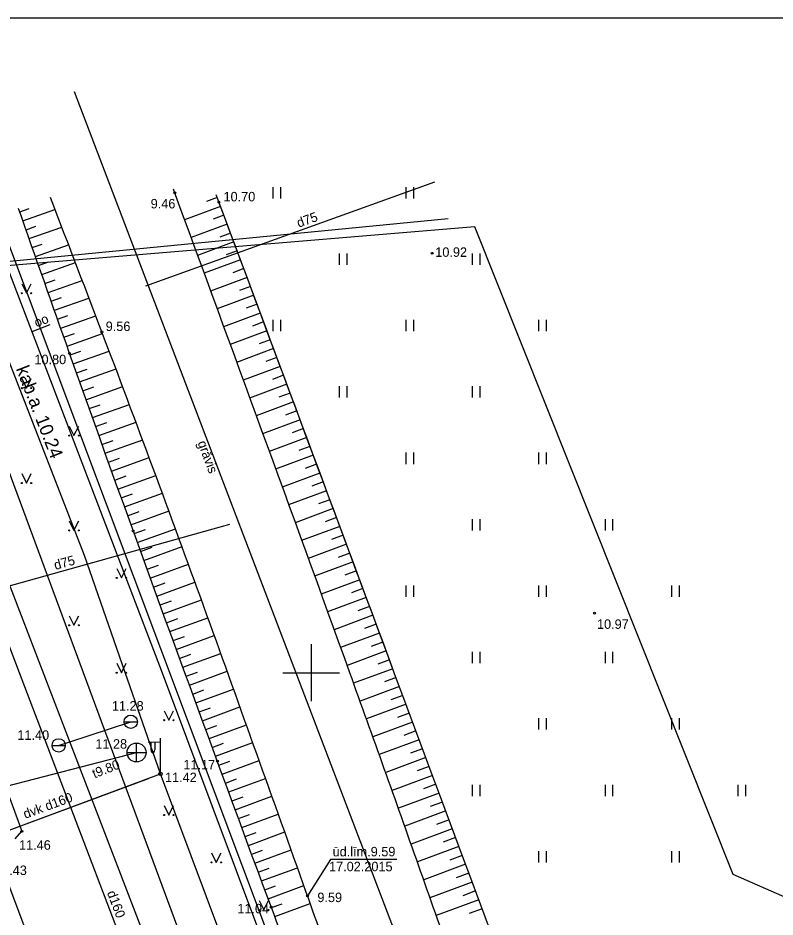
# Model space of a CAD drawing. Extents: x 503353 to 504004, y 304662 to 305049.
# Drawn here: x 503384.55 to 503424.44, y 304987.12 to 305034.51 of the extents above; entities that cross this region are included whole.
import ezdxf

# ---------------------------------------------------------------- set-up
doc = ezdxf.new("R2010")
doc.units = 0
for name, color, linetype in [('25', 7, 'Continuous'), ('APGR_SARK_####_####_#', 7, 'Continuous'), ('APGS_ACRL_####_####_#', 7, 'Continuous'), ('APGS_ACRL_####_TKST_#', 7, 'Continuous'), ('APGS_ELEM_####_####_#', 7, 'Continuous'), ('APGS_VADP_ZSPR_####_#', 7, 'Continuous'), ('APGS_VADP_ZSPR_TKST_#', 7, 'Continuous'), ('CELI_CMAL_####_####_#', 7, 'Continuous'), ('DREN_VADP_KLKT_####_#', 7, 'Continuous'), ('DREN_VADP_KLKT_TKST_#', 7, 'Continuous'), ('ELEK_VADP_ZSPR_####_#', 7, 'Continuous'), ('GAZE_VADP_VSP2_####_#', 7, 'Continuous'), ('GAZE_VADP_VSP2_TKST_#', 7, 'Continuous'), ('GEOD_ELEM_####_####_#', 7, 'Continuous'), ('HIDG_GRAV_####_TKST_#', 7, 'Continuous'), ('HIDG_PLIN_####_####_#', 7, 'Continuous'), ('HIDG_UATZ_####_TKST_#', 7, 'Continuous'), ('RAMI_PLAN_####_TKST_#', 7, 'Continuous'), ('RAMI_UZMR_####_####_#', 7, 'Continuous'), ('RELJ_AATZ_####_TKST_#', 7, 'Continuous'), ('RELJ_ELEM_####_####_#', 7, 'Continuous'), ('RELJ_NOGA_####_####_#', 7, 'Continuous'), ('SAKK_IZVK_####_TKST_#', 7, 'Continuous'), ('SAKK_KKAN_####_####_#', 7, 'Continuous'), ('SKAN_ELEM_####_####_#', 7, 'Continuous'), ('SKAN_ELEM_PAST_TKST_#', 7, 'Continuous'), ('SKAN_VADP_PAST_####_#', 7, 'Continuous'), ('SKAN_VADP_PAST_TKST_#', 7, 'Continuous'), ('TERT_ELEM_####_####_#', 7, 'Continuous'), ('UDTK_ELEM_####_####_#', 7, 'Continuous'), ('UDTK_ELEM_####_TKST_#', 7, 'Continuous'), ('UDTK_VADP_UDEN_####_#', 7, 'Continuous')]:
    doc.layers.add(name, color=color, linetype=linetype)

msp = doc.modelspace()

# ---------------------------------------------------------------- linework, layer by layer
at = {"layer": '25'}
for p, q in [((503395.906, 305008.647), (503387.533, 305030.611)), ((503405.924, 304982.367), (503395.906, 305008.647))]:
    msp.add_line(p, q, dxfattribs=at)
at = {"layer": 'APGR_SARK_####_####_#'}
msp.add_line((503382.16, 305027.621), (503400.006, 304980.111), dxfattribs=at)
at = {"layer": 'APGS_ACRL_####_####_#'}
msp.add_line((503382.983, 304991.303), (503391.423, 304994.43), dxfattribs=at)
at = {"layer": 'APGS_ELEM_####_####_#'}
for p, q in [((503392.05, 304996.333), (503391.415, 304996.328)), ((503391.55, 304996.329), (503391.55, 304995.937)), ((503391.76, 304996.331), (503391.76, 304995.937)), ((503392.059, 304994.666), (503392.057, 304996.549))]:
    msp.add_line(p, q, dxfattribs=at)
msp.add_circle((503392.059, 304994.666), 0.0907, dxfattribs=at)
msp.add_ellipse((503391.655, 304995.937), major_axis=(0, 0.151), ratio=0.695971, start_param=1.570796, end_param=4.712389, dxfattribs=at)
at = {"layer": 'APGS_VADP_ZSPR_####_#'}
for p, q in [((503388.049, 305006.178), (503380.972, 305024.384)), ((503390.197, 305000.011), (503388.049, 305006.178)), ((503392.059, 304994.666), (503390.197, 305000.011)), ((503382.828, 304991.246), (503392.059, 304994.666)), ((503395.411, 304985.727), (503392.059, 304994.666))]:
    msp.add_line(p, q, dxfattribs=at)
at = {"layer": 'CELI_CMAL_####_####_#'}
for points in [[(503393.097, 304986.219), (503379.573, 305022.746)], [(503373.677, 305021.537), (503382.111, 304998.789), (503384.746, 304991.641)], [(503384.397, 304991.238), (503384.746, 304991.641)]]:
    msp.add_lwpolyline(points, dxfattribs=at)
at = {"layer": 'DREN_VADP_KLKT_####_#'}
msp.add_line((503371.327, 305001.016), (503395.713, 305007.825), dxfattribs=at)
msp.add_lwpolyline([(503391.291, 305020.385), (503406.513, 305025.881)], dxfattribs=at)
at = {"layer": 'ELEK_VADP_ZSPR_####_#'}
msp.add_lwpolyline([(503379.852, 305000), (503395.709, 304957.709)], dxfattribs=at)
at = {"layer": 'GAZE_VADP_VSP2_####_#'}
msp.add_line((503394.546, 304974.002), (503384.635, 305000), dxfattribs=at)
msp.add_lwpolyline([(503384.635, 305000), (503375.541, 305023.856)], dxfattribs=at)
at = {"layer": 'GEOD_ELEM_####_####_#'}
for p, q in [((503400, 305001.5), (503400, 305000)), ((503398.5, 305000), (503400, 305000)), ((503400, 305000), (503400, 304998.5)), ((503400, 305000), (503401.5, 305000))]:
    msp.add_line(p, q, dxfattribs=at)
at = {"layer": 'HIDG_PLIN_####_####_#'}
for points in [[(503411.469, 304955.877), (503406.678, 304968.605), (503404.887, 304973.537), (503403.172, 304978.498), (503401.476, 304983.466), (503399.743, 304988.42), (503397.13, 304995.726), (503394.508, 305003.029), (503389.116, 305017.581), (503386.254, 305025.055)], [(503419.587, 304952.537), (503416.755, 304959.536), (503412.876, 304969.575), (503409.221, 304979.701), (503405.654, 304989.86), (503402.036, 305000), (503392.74, 305025.488)]]:
    msp.add_spline(points, degree=3, dxfattribs=at)
at = {"layer": 'HIDG_UATZ_####_TKST_#'}
msp.add_lwpolyline([(503404.518, 304990.157), (503401.015, 304990.157), (503399.81, 304988.233)], dxfattribs=at)
at = {"layer": 'RAMI_PLAN_####_TKST_#'}
msp.add_lwpolyline([(503550.18, 304891.905), (503352.996, 304891.905), (503352.996, 305034.51), (503550.18, 305034.51)], close=True, dxfattribs=at)
at = {"layer": 'RAMI_UZMR_####_####_#'}
for points in [[(503407.219, 305023.925), (503368.776, 305020.183), (503379.431, 304977.462), (503383.452, 304957.421), (503396.867, 304960.598), (503416.959, 304959.032), (503433.698, 304951.36), (503608.791, 304871.751), (503642.724, 304858.177), (503694.651, 304834.724), (503842.283, 304765.867)], [(503825.923, 304784.828), (503697.433, 304847.709), (503608.51, 304889.842), (503606.524, 304897.202), (503679.244, 304999.942), (503684.897, 305009.76), (503666.777, 305017.939), (503656.134, 304996.39), (503644.103, 304987.6), (503600.987, 304924.263), (503587.985, 304916.668), (503422.237, 304989.372), (503408.615, 305023.495), (503368.776, 305020.183)]]:
    msp.add_lwpolyline(points, dxfattribs=at)
at = {"layer": 'RELJ_ELEM_####_####_#'}
for centre in [(503392.81, 305025.296), (503395.14, 305024.807), (503406.37, 305022.106), (503388.971, 305017.959), (503387.268, 305016.834), (503390.616, 305007.472), (503414.935, 305003.134), (503395.057, 304995.339), (503384.746, 304991.641), (503399.81, 304988.233), (503397.891, 304987.648)]:
    msp.add_circle(centre, 0.05, dxfattribs=at)
at = {"layer": 'RELJ_NOGA_####_####_#'}
for p, q in [((503395.05, 305025.048), (503394.482, 305024.837)), ((503395.225, 305024.58), (503393.329, 305023.873)), ((503384.64, 305024.294), (503385.144, 305024.471)), ((503384.806, 305023.822), (503386.498, 305024.418)), ((503395.399, 305024.111), (503394.83, 305023.899)), ((503395.574, 305023.642), (503393.671, 305022.934)), ((503384.973, 305023.351), (503385.484, 305023.531)), ((503385.139, 305022.879), (503386.856, 305023.484)), ((503395.748, 305023.174), (503395.177, 305022.961)), ((503395.923, 305022.705), (503394.014, 305021.994)), ((503385.305, 305022.407), (503385.824, 305022.59)), ((503385.471, 305021.936), (503387.213, 305022.55)), ((503396.097, 305022.237), (503395.524, 305022.023)), ((503396.272, 305021.768), (503394.357, 305021.055)), ((503385.637, 305021.464), (503386.164, 305021.65)), ((503385.803, 305020.993), (503387.571, 305021.615)), ((503396.446, 305021.3), (503395.871, 305021.085)), ((503396.621, 305020.831), (503394.699, 305020.115)), ((503385.969, 305020.521), (503386.503, 305020.709)), ((503386.135, 305020.049), (503387.929, 305020.681)), ((503396.795, 305020.362), (503396.218, 305020.147)), ((503396.97, 305019.894), (503395.042, 305019.176)), ((503386.301, 305019.578), (503386.843, 305019.769)), ((503386.468, 305019.106), (503388.287, 305019.747)), ((503397.144, 305019.425), (503396.565, 305019.21)), ((503397.319, 305018.957), (503395.385, 305018.237)), ((503386.634, 305018.635), (503387.183, 305018.828)), ((503386.8, 305018.163), (503388.644, 305018.813)), ((503397.493, 305018.488), (503396.912, 305018.272)), ((503397.668, 305018.02), (503395.727, 305017.297)), ((503386.966, 305017.691), (503387.523, 305017.888)), ((503387.132, 305017.22), (503389.002, 305017.879)), ((503397.842, 305017.551), (503397.259, 305017.334)), ((503398.017, 305017.083), (503396.07, 305016.358)), ((503387.298, 305016.748), (503387.863, 305016.948)), ((503387.465, 305016.277), (503389.358, 305016.946)), ((503398.191, 305016.614), (503397.606, 305016.396)), ((503398.366, 305016.145), (503396.413, 305015.418)), ((503387.631, 305015.805), (503388.203, 305016.007)), ((503387.798, 305015.334), (503389.714, 305016.011)), ((503398.54, 305015.677), (503397.953, 305015.458)), ((503398.715, 305015.208), (503396.755, 305014.479)), ((503387.965, 305014.863), (503388.543, 305015.068)), ((503388.133, 305014.392), (503390.068, 305015.08)), ((503398.889, 305014.74), (503398.301, 305014.521)), ((503388.467, 305013.449), (503390.421, 305014.144)), ((503399.064, 305014.271), (503397.098, 305013.539)), ((503388.3, 305013.921), (503388.883, 305014.128)), ((503399.238, 305013.803), (503398.648, 305013.583)), ((503388.635, 305012.978), (503389.223, 305013.188)), ((503388.804, 305012.508), (503390.771, 305013.21)), ((503399.413, 305013.334), (503397.441, 305012.6)), ((503399.587, 305012.866), (503398.995, 305012.645)), ((503388.972, 305012.037), (503389.564, 305012.249)), ((503389.141, 305011.566), (503391.12, 305012.276)), ((503399.762, 305012.397), (503397.783, 305011.66)), ((503399.936, 305011.928), (503399.342, 305011.707)), ((503389.31, 305011.095), (503389.905, 305011.309)), ((503389.478, 305010.625), (503391.47, 305011.339)), ((503400.111, 305011.46), (503398.126, 305010.721)), ((503400.285, 305010.991), (503399.689, 305010.769)), ((503389.648, 305010.154), (503390.246, 305010.37)), ((503389.817, 305009.684), (503391.816, 305010.404)), ((503400.46, 305010.523), (503398.469, 305009.781)), ((503400.634, 305010.054), (503400.036, 305009.831)), ((503389.987, 305009.214), (503390.588, 305009.43)), ((503390.156, 305008.743), (503392.163, 305009.466)), ((503400.809, 305009.586), (503398.811, 305008.842)), ((503400.983, 305009.117), (503400.383, 305008.894)), ((503390.326, 305008.273), (503390.929, 305008.491)), ((503390.496, 305007.803), (503392.507, 305008.53)), ((503401.158, 305008.649), (503399.154, 305007.902)), ((503401.332, 305008.18), (503400.73, 305007.956)), ((503390.667, 305007.333), (503391.27, 305007.552)), ((503390.837, 305006.863), (503392.851, 305007.593)), ((503401.507, 305007.711), (503399.497, 305006.963)), ((503401.682, 305007.243), (503401.077, 305007.018)), ((503391.008, 305006.393), (503391.612, 305006.612)), ((503391.178, 305005.923), (503393.193, 305006.656)), ((503401.856, 305006.774), (503399.839, 305006.023)), ((503402.031, 305006.306), (503401.425, 305006.08)), ((503391.349, 305005.453), (503391.954, 305005.673)), ((503391.52, 305004.983), (503393.535, 305005.716)), ((503402.205, 305005.837), (503400.182, 305005.084)), ((503402.38, 305005.369), (503401.772, 305005.142)), ((503391.691, 305004.513), (503392.296, 305004.733)), ((503391.863, 305004.043), (503393.876, 305004.778)), ((503402.554, 305004.9), (503400.525, 305004.144)), ((503402.729, 305004.432), (503402.119, 305004.204)), ((503392.034, 305003.574), (503392.638, 305003.794)), ((503392.206, 305003.104), (503394.216, 305003.838)), ((503402.903, 305003.963), (503400.867, 305003.205)), ((503403.078, 305003.494), (503402.466, 305003.267)), ((503392.377, 305002.634), (503392.979, 305002.855)), ((503392.549, 305002.165), (503394.555, 305002.899)), ((503403.252, 305003.026), (503401.21, 305002.265)), ((503403.427, 305002.557), (503402.813, 305002.329)), ((503392.721, 305001.695), (503393.322, 305001.915)), ((503392.893, 305001.226), (503394.893, 305001.958)), ((503403.601, 305002.089), (503401.552, 305001.326)), ((503403.776, 305001.62), (503403.16, 305001.391)), ((503393.065, 305000.756), (503393.664, 305000.976)), ((503393.237, 305000.287), (503395.231, 305001.019)), ((503403.95, 305001.152), (503401.895, 305000.386)), ((503404.125, 305000.683), (503403.507, 305000.453)), ((503393.409, 304999.818), (503394.007, 305000.037)), ((503393.582, 304999.348), (503395.569, 305000.078)), ((503404.299, 305000.214), (503402.237, 304999.446)), ((503404.474, 304999.746), (503403.854, 304999.515)), ((503393.754, 304998.879), (503394.349, 304999.097)), ((503393.926, 304998.409), (503395.907, 304999.137)), ((503404.648, 304999.277), (503402.578, 304998.507)), ((503404.822, 304998.809), (503404.2, 304998.577)), ((503394.099, 304997.94), (503394.692, 304998.158)), ((503394.272, 304997.471), (503396.244, 304998.197)), ((503404.997, 304998.34), (503402.917, 304997.566)), ((503405.171, 304997.871), (503404.545, 304997.639)), ((503394.444, 304997.002), (503395.035, 304997.219)), ((503394.617, 304996.533), (503396.582, 304997.256)), ((503405.345, 304997.403), (503403.254, 304996.625)), ((503405.52, 304996.934), (503404.89, 304996.7)), ((503394.79, 304996.063), (503395.378, 304996.28)), ((503394.962, 304995.594), (503396.919, 304996.315)), ((503405.694, 304996.466), (503403.59, 304995.683)), ((503405.868, 304995.997), (503405.235, 304995.762)), ((503395.135, 304995.125), (503395.721, 304995.341)), ((503395.308, 304994.656), (503397.256, 304995.374)), ((503406.043, 304995.528), (503403.925, 304994.741)), ((503406.217, 304995.06), (503405.579, 304994.823)), ((503395.481, 304994.187), (503396.064, 304994.402)), ((503395.654, 304993.718), (503397.593, 304994.432)), ((503406.391, 304994.591), (503404.259, 304993.799)), ((503406.565, 304994.122), (503405.923, 304993.884)), ((503395.827, 304993.248), (503396.408, 304993.462)), ((503396, 304992.779), (503397.931, 304993.491)), ((503406.739, 304993.654), (503404.593, 304992.856)), ((503406.913, 304993.185), (503406.267, 304992.945)), ((503396.173, 304992.31), (503396.751, 304992.523)), ((503396.346, 304991.841), (503398.268, 304992.549)), ((503407.088, 304992.716), (503404.927, 304991.913)), ((503407.262, 304992.247), (503406.611, 304992.006)), ((503396.519, 304991.372), (503397.094, 304991.584)), ((503396.692, 304990.903), (503398.604, 304991.608)), ((503407.436, 304991.779), (503405.26, 304990.971)), ((503407.61, 304991.31), (503406.955, 304991.067)), ((503396.865, 304990.434), (503397.437, 304990.645)), ((503397.038, 304989.964), (503398.941, 304990.666)), ((503407.784, 304990.841), (503405.594, 304990.028)), ((503407.958, 304990.373), (503407.299, 304990.128)), ((503397.211, 304989.495), (503397.78, 304989.705)), ((503397.384, 304989.026), (503399.278, 304989.724)), ((503408.132, 304989.904), (503405.927, 304989.085)), ((503408.306, 304989.435), (503407.642, 304989.189)), ((503397.557, 304988.557), (503398.123, 304988.766)), ((503397.73, 304988.088), (503399.614, 304988.782)), ((503408.48, 304988.966), (503406.26, 304988.142)), ((503408.654, 304988.498), (503407.986, 304988.249)), ((503397.902, 304987.619), (503398.466, 304987.826)), ((503398.075, 304987.15), (503399.949, 304987.84)), ((503408.828, 304988.029), (503406.591, 304987.198)), ((503409.002, 304987.56), (503408.329, 304987.31))]:
    msp.add_line(p, q, dxfattribs=at)
for points in [[(503421.793, 304953.375), (503418.978, 304960.8), (503411.664, 304980.395), (503404.379, 305000), (503394.998, 305025.189)], [(503421.793, 304953.375), (503418.978, 304960.8), (503411.664, 304980.395), (503404.379, 305000), (503395.14, 305024.807)], [(503410.247, 304955.404), (503401.902, 304976.94), (503397.494, 304988.727), (503387.268, 305016.834), (503384.58, 305024.465)]]:
    msp.add_spline(points, degree=3, dxfattribs=at)
at = {"layer": 'SAKK_IZVK_####_TKST_#'}
msp.add_line((503386.228, 305018.34), (503385.273, 305017.975), dxfattribs=at)
at = {"layer": 'SAKK_KKAN_####_####_#'}
for points in [[(503382.758, 305024.558), (503392.141, 305000)], [(503392.141, 305000), (503403.85, 304968.741), (503409.025, 304954.715)]]:
    msp.add_lwpolyline(points, dxfattribs=at)
at = {"layer": 'SKAN_ELEM_####_####_#'}
for p, q in [((503390.798, 304995.296), (503390.798, 304996.296)), ((503390.298, 304995.796), (503391.298, 304995.796))]:
    msp.add_line(p, q, dxfattribs=at)
msp.add_circle((503390.798, 304995.796), 0.5, dxfattribs=at)
at = {"layer": 'SKAN_VADP_PAST_####_#'}
msp.add_line((503379.98, 304993.004), (503390.798, 304995.796), dxfattribs=at)
at = {"layer": 'TERT_ELEM_####_####_#'}
for p, q in [((503398, 305025), (503398, 305025.6)), ((503398.4, 305025), (503398.4, 305025.6)), ((503405, 305025), (503405, 305025.6)), ((503405.4, 305025), (503405.4, 305025.6)), ((503401.5, 305021.5), (503401.5, 305022.1)), ((503401.9, 305021.5), (503401.9, 305022.1)), ((503408.5, 305021.5), (503408.5, 305022.1)), ((503408.9, 305021.5), (503408.9, 305022.1)), ((503384.75, 305020.5), (503385, 305020)), ((503385, 305020), (503385.25, 305020.5)), ((503398, 305018), (503398, 305018.6)), ((503398.4, 305018), (503398.4, 305018.6)), ((503405, 305018), (503405, 305018.6)), ((503405.4, 305018), (503405.4, 305018.6)), ((503412, 305018), (503412, 305018.6)), ((503412.4, 305018), (503412.4, 305018.6)), ((503384.75, 305015.5), (503385, 305015)), ((503385, 305015), (503385.25, 305015.5)), ((503401.5, 305014.5), (503401.5, 305015.1)), ((503401.9, 305014.5), (503401.9, 305015.1)), ((503408.5, 305014.5), (503408.5, 305015.1)), ((503408.9, 305014.5), (503408.9, 305015.1)), ((503387.25, 305013), (503387.5, 305012.5)), ((503387.5, 305012.5), (503387.75, 305013)), ((503405, 305011), (503405, 305011.6)), ((503405.4, 305011), (503405.4, 305011.6)), ((503412, 305011), (503412, 305011.6)), ((503412.4, 305011), (503412.4, 305011.6)), ((503384.75, 305010.5), (503385, 305010)), ((503385, 305010), (503385.25, 305010.5)), ((503387.25, 305008), (503387.5, 305007.5)), ((503387.5, 305007.5), (503387.75, 305008)), ((503408.5, 305007.5), (503408.5, 305008.1)), ((503408.9, 305007.5), (503408.9, 305008.1)), ((503415.5, 305007.5), (503415.5, 305008.1)), ((503415.9, 305007.5), (503415.9, 305008.1)), ((503389.75, 305005.5), (503390, 305005)), ((503390, 305005), (503390.25, 305005.5)), ((503405, 305004), (503405, 305004.6)), ((503405.4, 305004), (503405.4, 305004.6)), ((503412, 305004), (503412, 305004.6)), ((503412.4, 305004), (503412.4, 305004.6)), ((503419, 305004), (503419, 305004.6)), ((503419.4, 305004), (503419.4, 305004.6)), ((503387.25, 305003), (503387.5, 305002.5)), ((503387.5, 305002.5), (503387.75, 305003)), ((503408.5, 305000.5), (503408.5, 305001.1)), ((503408.9, 305000.5), (503408.9, 305001.1)), ((503415.5, 305000.5), (503415.5, 305001.1)), ((503415.9, 305000.5), (503415.9, 305001.1)), ((503389.75, 305000.5), (503390, 305000)), ((503390, 305000), (503390.25, 305000.5)), ((503392.25, 304998), (503392.5, 304997.5)), ((503392.5, 304997.5), (503392.75, 304998)), ((503412, 304997), (503412, 304997.6)), ((503412.4, 304997), (503412.4, 304997.6)), ((503419, 304997), (503419, 304997.6)), ((503419.4, 304997), (503419.4, 304997.6)), ((503408.5, 304993.5), (503408.5, 304994.1)), ((503408.9, 304993.5), (503408.9, 304994.1)), ((503415.5, 304993.5), (503415.5, 304994.1)), ((503415.9, 304993.5), (503415.9, 304994.1)), ((503422.5, 304993.5), (503422.5, 304994.1)), ((503422.9, 304993.5), (503422.9, 304994.1)), ((503392.25, 304993), (503392.5, 304992.5)), ((503392.5, 304992.5), (503392.75, 304993)), ((503394.75, 304990.5), (503395, 304990)), ((503395, 304990), (503395.25, 304990.5)), ((503412, 304990), (503412, 304990.6)), ((503412.4, 304990), (503412.4, 304990.6)), ((503419, 304990), (503419, 304990.6)), ((503419.4, 304990), (503419.4, 304990.6)), ((503397.25, 304988), (503397.5, 304987.5)), ((503397.5, 304987.5), (503397.75, 304988))]:
    msp.add_line(p, q, dxfattribs=at)
for centre, radius in [((503384.75, 305020), 0.028), ((503385.25, 305020), 0.0263), ((503384.75, 305015), 0.028), ((503385.25, 305015), 0.0263), ((503387.25, 305012.5), 0.028), ((503387.75, 305012.5), 0.0263), ((503384.75, 305010), 0.028), ((503385.25, 305010), 0.0263), ((503387.25, 305007.5), 0.028), ((503387.75, 305007.5), 0.0263), ((503389.75, 305005), 0.028), ((503390.25, 305005), 0.0263), ((503387.25, 305002.5), 0.028), ((503387.75, 305002.5), 0.0263), ((503389.75, 305000), 0.028), ((503390.25, 305000), 0.0263), ((503392.25, 304997.5), 0.028), ((503392.75, 304997.5), 0.0263), ((503392.25, 304992.5), 0.028), ((503392.75, 304992.5), 0.0263), ((503394.75, 304990), 0.028), ((503395.25, 304990), 0.0263), ((503397.25, 304987.5), 0.028), ((503397.75, 304987.5), 0.0263)]:
    msp.add_circle(centre, radius, dxfattribs=at)
at = {"layer": 'UDTK_ELEM_####_####_#'}
for p, q in [((503390.139, 304997.417), (503390.839, 304997.417)), ((503390.489, 304997.416), (503390.489, 304997.417)), ((503386.342, 304996.173), (503387.042, 304996.173)), ((503386.692, 304996.172), (503386.692, 304996.173))]:
    msp.add_line(p, q, dxfattribs=at)
for centre in [(503390.49, 304997.416), (503386.693, 304996.172)]:
    msp.add_circle(centre, 0.351, dxfattribs=at)
at = {"layer": 'UDTK_VADP_UDEN_####_#'}
for p, q in [((503387.232, 304996.349), (503390.49, 304997.416)), ((503386.692, 304996.173), (503387.232, 304996.348))]:
    msp.add_line(p, q, dxfattribs=at)
msp.add_lwpolyline([(503376.794, 305023.6), (503396.075, 304973.418)], dxfattribs=at)

# ---------------------------------------------------------------- texts
at = {"layer": 'APGS_ACRL_####_TKST_#'}
msp.add_text('dvk d160', height=0.5, rotation=20.3294, dxfattribs=at).set_placement((503384.935, 304992.296))
at = {"layer": 'APGS_VADP_ZSPR_TKST_#'}
msp.add_text('kab.a. 10.24', height=0.69994, rotation=291.2428, dxfattribs=at).set_placement((503384.432, 305016.023))
at = {"layer": 'DREN_VADP_KLKT_TKST_#'}
for rotation, p in [(19.853, (503399.345, 305023.452)), (15.6016, (503386.523, 305005.415))]:
    msp.add_text('d75', height=0.5, rotation=rotation, dxfattribs=at).set_placement(p)
at = {"layer": 'GAZE_VADP_VSP2_TKST_#'}
msp.add_text('d160', height=0.5, rotation=290.8678, dxfattribs=at).set_placement((503389.23, 304988.41))
at = {"layer": 'HIDG_GRAV_####_TKST_#'}
msp.add_text('grāvis', height=0.5, rotation=290.2983, dxfattribs=at).set_placement((503394.007, 305012.128))
at = {"layer": 'HIDG_UATZ_####_TKST_#'}
for s, p in [('ūd.līm.9.59', (503401.129, 304990.322)), ('17.02.2015', (503400.94, 304989.537))]:
    msp.add_text(s, height=0.5, dxfattribs=at).set_placement(p)
at = {"layer": 'RELJ_AATZ_####_TKST_#'}
for s, p in [('10.70', (503395.38, 305024.843)), ('9.46', (503391.541, 305024.473)), ('10.92', (503406.538, 305021.92)), ('9.56', (503389.171, 305018.009)), ('10.80', (503385.415, 305016.262)), ('10.97', (503415.061, 305002.313)), ('11.17', (503393.264, 304994.903)), (' 11.42', (503392.109, 304994.233)), (' 11.46', (503384.418, 304990.671)), (' 11.43', (503383.156, 304989.338)), ('9.59', (503400.326, 304987.911)), ('11.04', (503396.107, 304987.318))]:
    msp.add_text(s, height=0.5, dxfattribs=at).set_placement(p)
at = {"layer": 'SAKK_IZVK_####_TKST_#'}
msp.add_text('oo', height=0.5, rotation=20.9109, dxfattribs=at).set_placement((503385.518, 305018.2))
at = {"layer": 'SKAN_ELEM_PAST_TKST_#'}
msp.add_text('11.28', height=0.5, dxfattribs=at).set_placement((503388.625, 304995.998))
at = {"layer": 'SKAN_VADP_PAST_TKST_#'}
msp.add_text('t9.80', height=0.5, rotation=21.5022, dxfattribs=at).set_placement((503388.58, 304994.426))
at = {"layer": 'UDTK_ELEM_####_TKST_#'}
for s, p in [('11.28', (503389.498, 304998.005)), (' 11.40', (503384.332, 304996.463))]:
    msp.add_text(s, height=0.5, dxfattribs=at).set_placement(p)

doc.saveas('drawing.dxf')
